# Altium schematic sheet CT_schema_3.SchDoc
size 493 x 398 mm
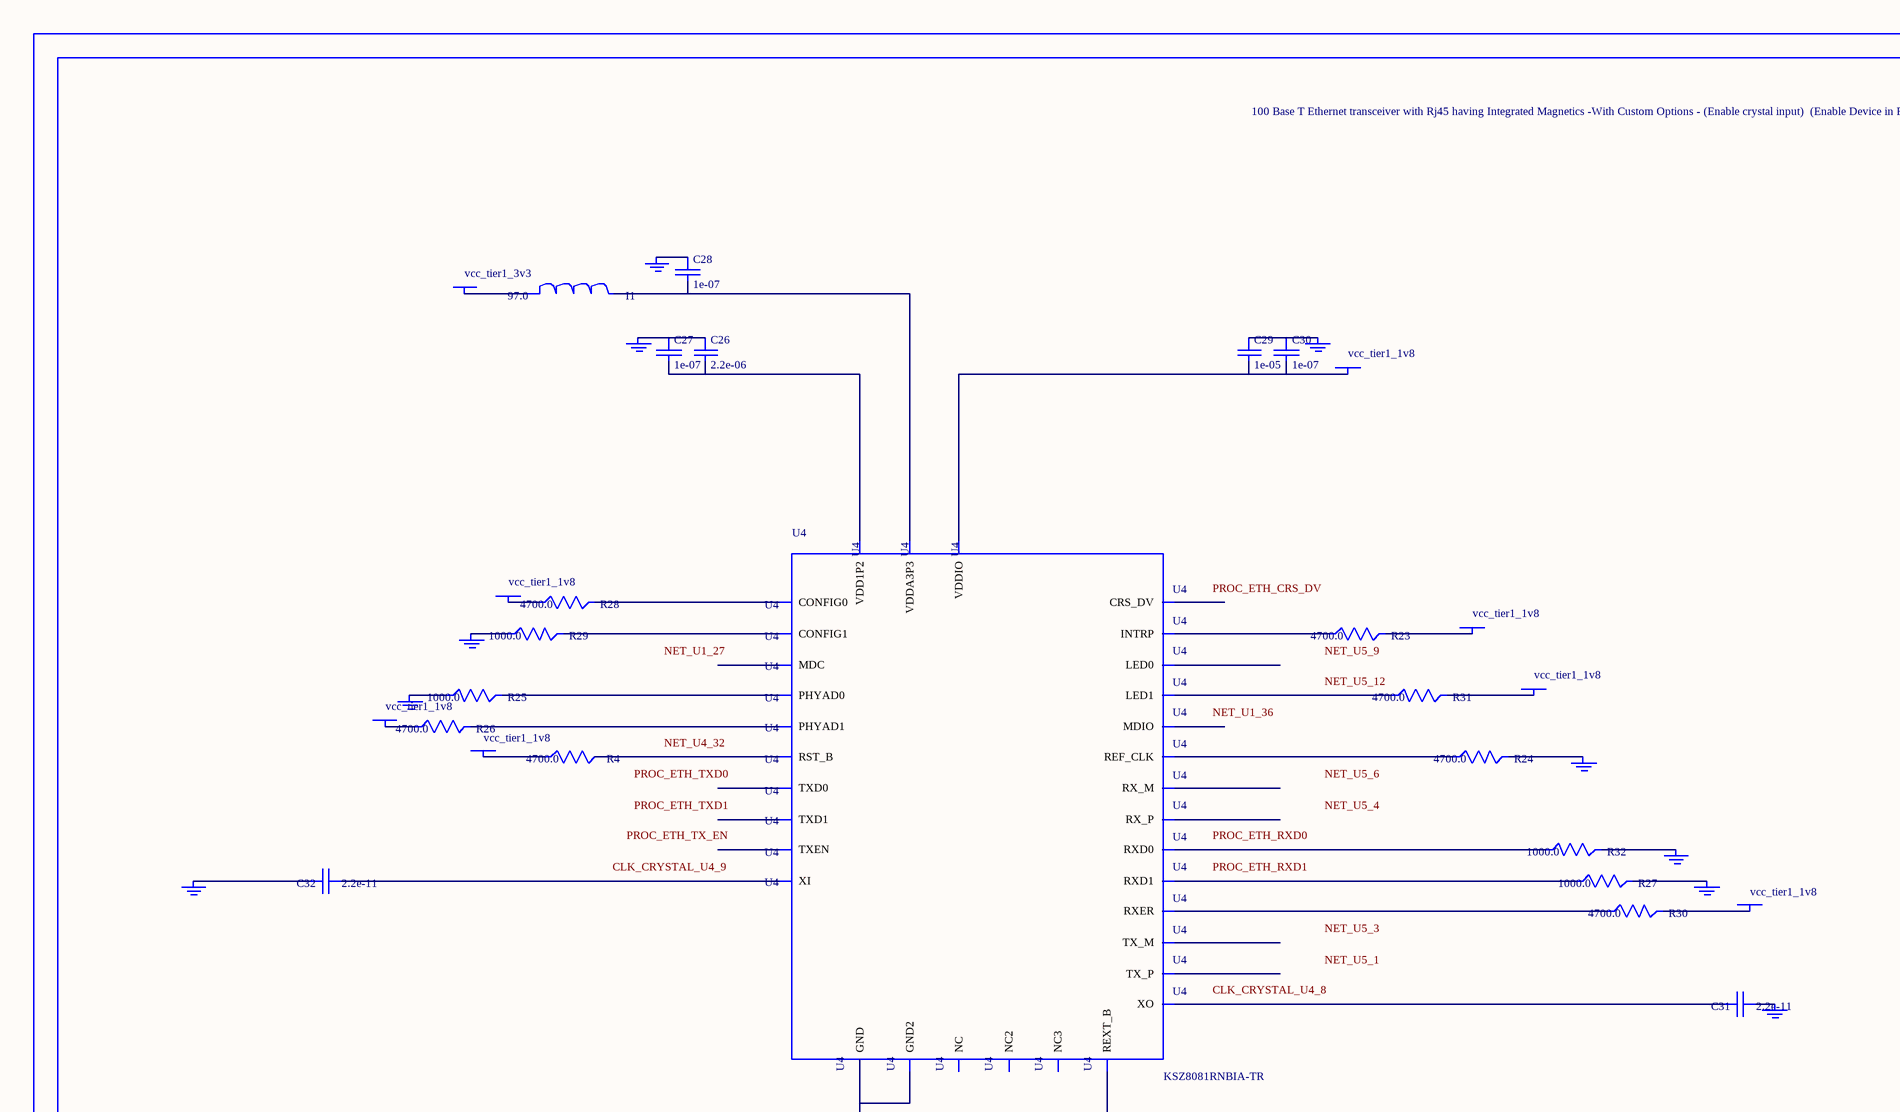
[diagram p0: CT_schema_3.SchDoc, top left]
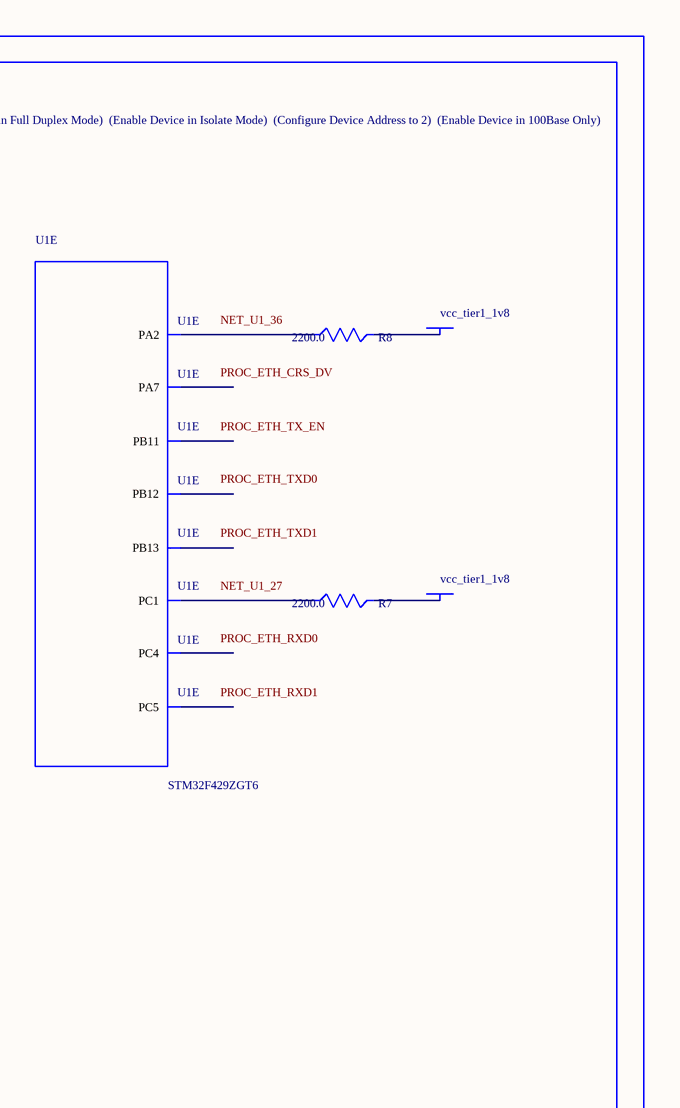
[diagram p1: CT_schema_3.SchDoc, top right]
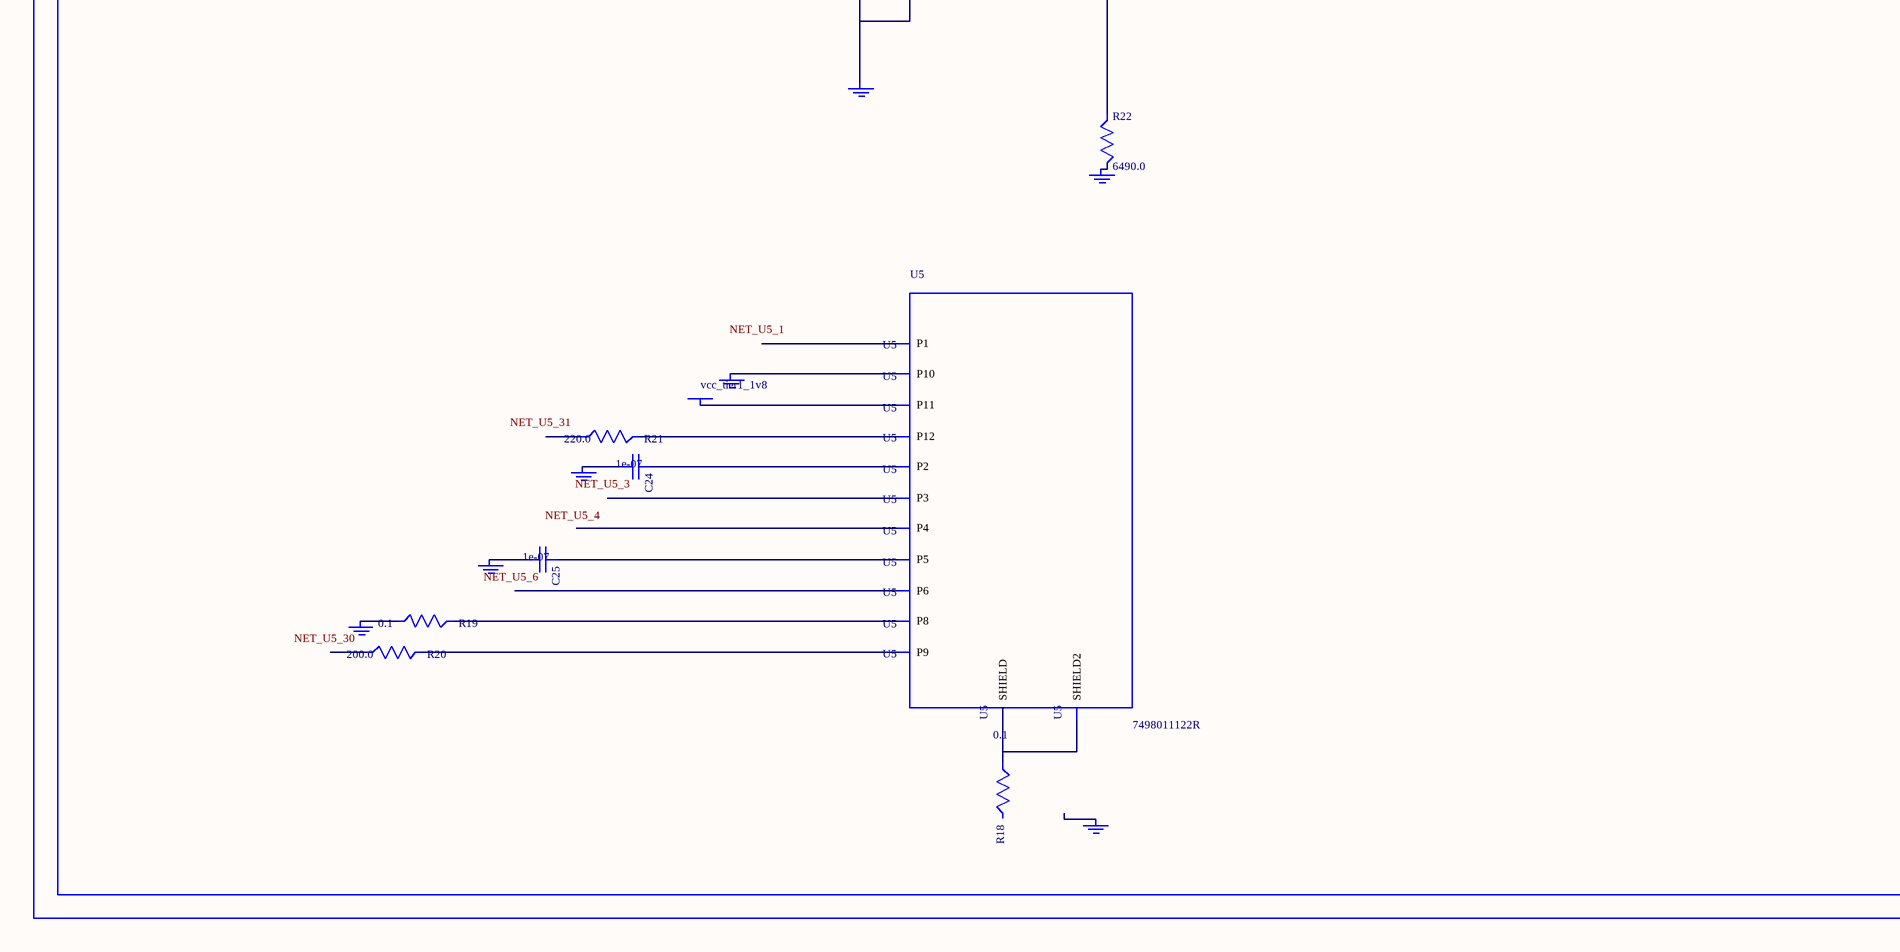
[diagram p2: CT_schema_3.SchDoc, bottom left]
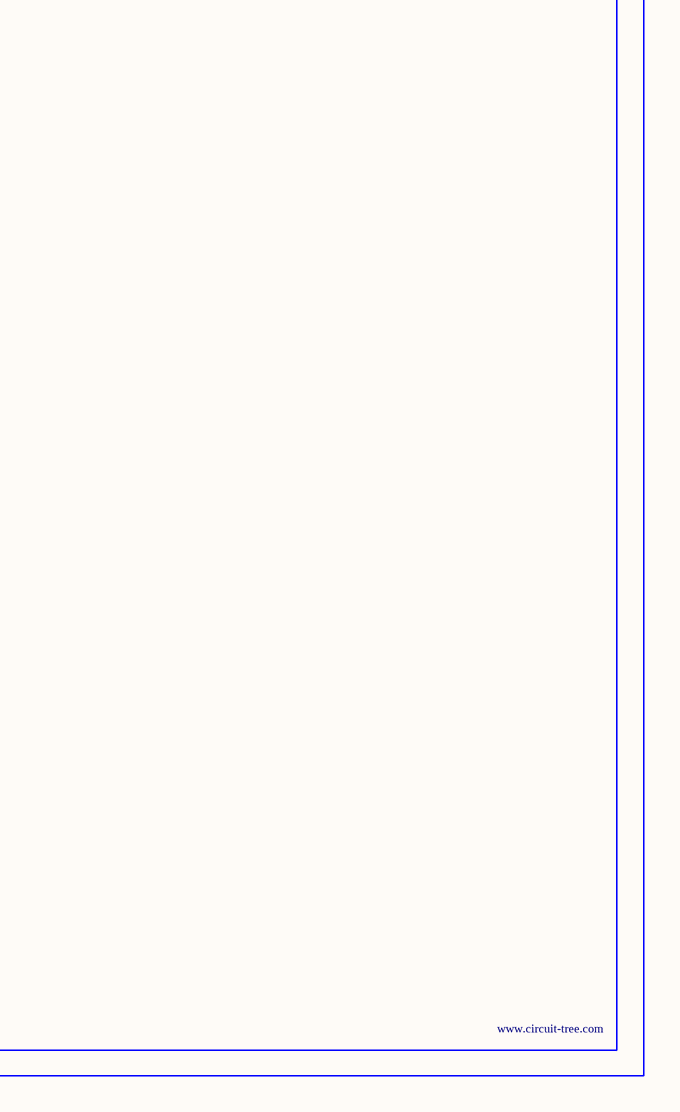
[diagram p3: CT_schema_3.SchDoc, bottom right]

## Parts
BORDER2  (no value)
C24  1e-07  [C0402]
C25  1e-07  [C0402]
C26  2.2e-06  [C0603]
C27  1e-07  [C0402]
C28  1e-07  [C0402]
C29  1e-05  [C0805]
C30  1e-07  [C0402]
C31  2.2e-11  [C0402]
C32  2.2e-11  [C0402]
GND_INSTANCE_2_0  (no value)
GND_INSTANCE_2_1  (no value)
GND_INSTANCE_2_2  (no value)
GND_INSTANCE_2_3  (no value)
GND_INSTANCE_2_4  (no value)
GND_INSTANCE_2_5  (no value)
GND_INSTANCE_2_6  (no value)
GND_INSTANCE_2_7  (no value)
GND_INSTANCE_2_8  (no value)
GND_INSTANCE_2_9  (no value)
GND_INSTANCE_2_10  (no value)
GND_INSTANCE_2_11  (no value)
GND_INSTANCE_2_12  (no value)
GND_INSTANCE_2_13  (no value)
GND_INSTANCE_2_14  (no value)
GND_INSTANCE_2_15  (no value)
GND_INSTANCE_2_16  (no value)
I1  97.0  [R0603]
POWER_INSTANCE_2_0  vcc_tier1_3v3
POWER_INSTANCE_2_1  vcc_tier1_1v8
POWER_INSTANCE_2_2  vcc_tier1_1v8
POWER_INSTANCE_2_3  vcc_tier1_1v8
POWER_INSTANCE_2_4  vcc_tier1_1v8
POWER_INSTANCE_2_5  vcc_tier1_1v8
POWER_INSTANCE_2_6  vcc_tier1_1v8
POWER_INSTANCE_2_7  vcc_tier1_1v8
POWER_INSTANCE_2_8  vcc_tier1_1v8
POWER_INSTANCE_2_9  vcc_tier1_1v8
POWER_INSTANCE_2_10  vcc_tier1_1v8
R4  4700.0  [R0603]
R7  2200.0  [R0603]
R8  2200.0  [R0603]
R18  0.1  [R0603]
R19  0.1  [R0603]
R20  200.0  [R0603]
R21  220.0  [R0603]
R22  6490.0  [R0603]
R23  4700.0  [R0603]
R24  4700.0  [R0603]
R25  1000.0  [R0603]
R26  4700.0  [R0603]
R27  1000.0  [R0603]
R28  4700.0  [R0603]
R29  1000.0  [R0603]
R30  4700.0  [R0603]
R31  4700.0  [R0603]
R32  1000.0  [R0603]
U1  STM32F429ZGT6  [LQFP144]  (part E of 11)
U4  KSZ8081RNBIA-TR  [QFN-32]
U5  7498011122R  [7498011122R]

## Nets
NetC24_1: C24.1 U5.2(P2)
NetC24_2: C24.2 GND_INSTANCE_2_12.0(GND)
NetC25_1: C25.1 U5.5(P5)
NetC25_2: C25.2 GND_INSTANCE_2_13.0(GND)
NetC26_1: C26.1 C27.1 GND_INSTANCE_2_0.0(GND)
NetC26_2: C26.2 C27.2 U4.2(VDD1P2)
NetC28_1: C28.1 GND_INSTANCE_2_1.0(GND)
NetC28_2: C28.2 I1.2 U4.3(VDDA3P3)
NetC29_1: C29.1 C30.1 GND_INSTANCE_2_8.0(GND)
NetC29_2: C29.2 C30.2 POWER_INSTANCE_2_2.0(PWR) U4.17(VDDIO)
NetC31_1: C31.1 GND_INSTANCE_2_2.0(GND)
NetC31_2: C31.2 U4.8(XO)
NetC32_1: C32.1 U4.9(XI)
NetC32_2: C32.2 GND_INSTANCE_2_3.0(GND)
NetGND_INSTANCE_2_4_0: GND_INSTANCE_2_4.0(GND) R22.2
NetGND_INSTANCE_2_5_0: GND_INSTANCE_2_5.0(GND) R25.1
NetGND_INSTANCE_2_6_0: GND_INSTANCE_2_6.0(GND) R27.2
NetGND_INSTANCE_2_7_0: GND_INSTANCE_2_7.0(GND) R32.2
NetGND_INSTANCE_2_9_0: GND_INSTANCE_2_9.0(GND) R24.2
NetGND_INSTANCE_2_10_0: GND_INSTANCE_2_10.0(GND) R29.1
NetGND_INSTANCE_2_11_0: GND_INSTANCE_2_11.0(GND) U4.1(GND) U4.EXP(GND2)
NetGND_INSTANCE_2_14_0: GND_INSTANCE_2_14.0(GND) R19.1
NetGND_INSTANCE_2_15_0: GND_INSTANCE_2_15.0(GND) U5.10(P10)
NetI1_1: I1.1 POWER_INSTANCE_2_0.0(PWR)
NetPOWER_INSTANCE_2_1_0: POWER_INSTANCE_2_1.0(PWR) R26.1
NetPOWER_INSTANCE_2_3_0: POWER_INSTANCE_2_3.0(PWR) R30.2
NetPOWER_INSTANCE_2_4_0: POWER_INSTANCE_2_4.0(PWR) R23.2
NetPOWER_INSTANCE_2_5_0: POWER_INSTANCE_2_5.0(PWR) R28.1
NetPOWER_INSTANCE_2_6_0: POWER_INSTANCE_2_6.0(PWR) R31.2
NetPOWER_INSTANCE_2_7_0: POWER_INSTANCE_2_7.0(PWR) R4.1
NetPOWER_INSTANCE_2_8_0: POWER_INSTANCE_2_8.0(PWR) R7.2
NetPOWER_INSTANCE_2_9_0: POWER_INSTANCE_2_9.0(PWR) R8.2
NetPOWER_INSTANCE_2_10_0: POWER_INSTANCE_2_10.0(PWR) U5.11(P11)
NetR4_2: R4.2 U4.32(RST_B)
NetR7_1: R7.1 U1.27(PC1)
NetR8_1: R8.1 U1.36(PA2)
NetR18_1: R18.1 U5.13(SHIELD) U5.14(SHIELD2)
NetR19_2: R19.2 U5.8(P8)
NetR20_2: R20.2 U5.9(P9)
NetR21_2: R21.2 U5.12(P12)
NetR22_1: R22.1 U4.10(REXT_B)
NetR23_1: R23.1 U4.21(INTRP)
NetR24_1: R24.1 U4.19(REF_CLK)
NetR25_2: R25.2 U4.13(PHYAD0)
NetR26_2: R26.2 U4.14(PHYAD1)
NetR27_1: R27.1 U4.15(RXD1)
NetR28_2: R28.2 U4.28(CONFIG0)
NetR29_2: R29.2 U4.29(CONFIG1)
NetR30_1: R30.1 U4.20(RXER)
NetR31_1: R31.1 U4.31(LED1)
NetR32_1: R32.1 U4.16(RXD0)

Not connected (* = marked no-connect by the designer): GND_INSTANCE_2_16 0(GND); R18 2; R20 1; R21 1; U1 43(PA7) 44(PC4) 45(PC5) 70(PB11) 73(PB12) 74(PB13); U4 4(RX_M) 5(RX_P) 6(TX_M) 7(TX_P) 11(MDIO) 12(MDC) 18(CRS_DV) 22(NC) 23(TXEN) 24(TXD0) 25(TXD1) 26(NC2) 27(NC3) 30(LED0); U5 1(P1) 3(P3) 4(P4) 6(P6)

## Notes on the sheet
- Labels drawn without touching a wire or pin: CLK_CRYSTAL_U4_8, CLK_CRYSTAL_U4_9, NET_U1_27, NET_U1_36, NET_U4_32, NET_U5_1, NET_U5_3, NET_U5_4, NET_U5_6, NET_U5_9, NET_U5_12, NET_U5_30, NET_U5_31, PROC_ETH_CRS_DV, PROC_ETH_RXD0, PROC_ETH_RXD1, PROC_ETH_TX_EN, PROC_ETH_TXD0, PROC_ETH_TXD1

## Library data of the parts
BORDER2 = BORDER_PAGE2
C24 C25 C27 C28 C30 = C0402C104K3RACTU
C26 = C0603C225K8RACTU
C29 = C0805C106K8RACTU
C31 C32 = C0402C220K3RAC
GND_INSTANCE_2_0-GND_INSTANCE_2_16 = GND
I1 = I1
POWER_INSTANCE_2_0-POWER_INSTANCE_2_10 = PWR
R4 R23 R24 R26 R28 R30 R31 = RC0603JR-074K7L
R7 R8 = RC0603JR-072K2L
R18 R19 = ERJ-3RSFR10V
R20 = RC0603JR-07200RL
R21 = RC0603JR-07220RL
R22 = ERJ-3EKF6491V
R25 R27 R29 R32 = RC0603JR-071KL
